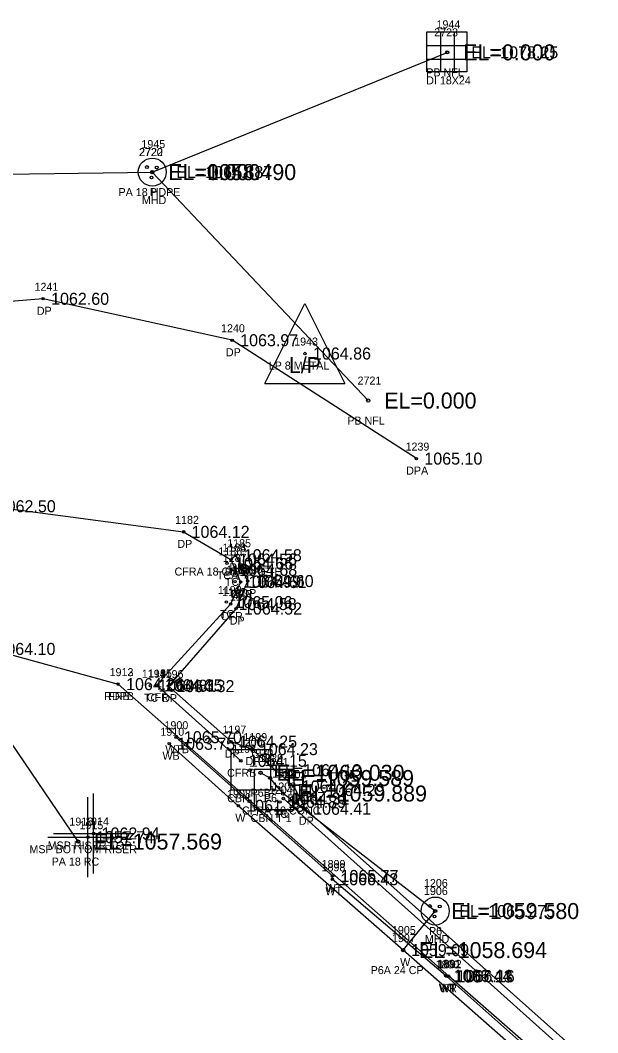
# Model space of a CAD drawing. Extents: x 1578957 to 1581675, y 1115963 to 1120391.
# Drawn here: x 1580412.6 to 1580484.8, y 1116687.4 to 1116814 of the extents above; entities that cross this region are included whole.
import ezdxf

# ---------------------------------------------------------------- set-up
doc = ezdxf.new("R2010")
doc.units = 0
for name, color, linetype in [('RD_EX_BldgApp', 7, 'Continuous'), ('RD_EX_Conc', 7, 'Continuous'), ('RD_EX_Conc_txCode', 7, 'Continuous'), ('RD_EX_DR_ErosCtrl', 7, 'Continuous'), ('RD_EX_DR_ErosCtrl_txCode', 7, 'Continuous'), ('RD_EX_DR_Inlet', 7, 'Continuous'), ('RD_EX_DR_Inlet_txCode', 7, 'Continuous'), ('RD_EX_DR_Pipe', 7, 'Continuous'), ('RD_EX_DR_Pipe_txCode', 7, 'Continuous'), ('RD_EX_Driveway', 7, 'Continuous'), ('RD_EX_Driveway_txCode', 7, 'Continuous'), ('RD_EX_Fence_Other', 7, 'Continuous'), ('RD_EX_Fence_Other_txCode', 7, 'Continuous'), ('RD_EX_Misc', 7, 'Continuous'), ('RD_EX_Misc_txCode', 7, 'Continuous'), ('RD_EX_TX_Conc_ELEV', 7, 'Continuous'), ('RD_EX_TX_DR_ErosCtrl_ELEV', 7, 'Continuous'), ('RD_EX_TX_DR_Inlet_ELEV', 7, 'Continuous'), ('RD_EX_TX_Driveway_ELEV', 7, 'Continuous'), ('RD_EX_TX_Fence_Other_ELEV', 7, 'Continuous'), ('RD_EX_TX_Misc_ELEV', 7, 'Continuous'), ('RD_EX_TX_UT_ELEV', 7, 'Continuous'), ('RD_EX_UT', 7, 'Continuous'), ('RD_EX_UT_txCode', 7, 'Continuous'), ('RD_SMD_Locator', 7, 'Continuous'), ('RD_TX_Pipe_ElevEX', 7, 'Continuous')]:
    doc.layers.add(name, color=color, linetype=linetype)

msp = doc.modelspace()

# ---------------------------------------------------------------- linework, layer by layer
at = {"layer": 'RD_EX_BldgApp'}
msp.add_lwpolyline([(1580452.9, 1116627.69), (1580465.65, 1116641.69), (1580491, 1116670.95), (1580460.48, 1116697.77), (1580439.88, 1116715.8), (1580431.25, 1116723.55)], dxfattribs=at)
at = {"layer": 'RD_EX_Conc'}
for points in [[(1580438.97, 1116746.57), (1580440.17, 1116743.76), (1580438.93, 1116741), (1580429.68, 1116730.86), (1580440.2, 1116721.42)], [(1580445.53, 1116716.71), (1580496.67, 1116670.92), (1580482, 1116654.67)]]:
    msp.add_lwpolyline(points, dxfattribs=at)
at = {"layer": 'RD_EX_DR_ErosCtrl'}
msp.add_lwpolyline([(1580451.64, 1116626.14), (1580425.19, 1116657.94), (1580401.68, 1116702.86), (1580396.66, 1116727.54), (1580408.78, 1116735.4), (1580424.86, 1116731)], dxfattribs=at)
at = {"layer": 'RD_EX_DR_Inlet'}
for p, q in [((1580465.16, 1116812.5), (1580465.16, 1116807.5)), ((1580466.86, 1116812.5), (1580466.86, 1116807.5)), ((1580463.46, 1116810.8), (1580468.46, 1116810.8)), ((1580463.46, 1116809.1), (1580468.46, 1116809.1)), ((1580443.96, 1116717.8), (1580443.96, 1116722.8)), ((1580446.88, 1116715.32), (1580446.88, 1116720.32))]:
    msp.add_line(p, q, dxfattribs=at)
for points in [[(1580463.46, 1116807.5), (1580463.46, 1116812.5), (1580468.46, 1116812.5), (1580468.46, 1116807.5)], [(1580443.96, 1116717.8), (1580443.96, 1116722.8), (1580438.96, 1116722.8), (1580438.96, 1116717.8)], [(1580446.88, 1116715.32), (1580446.88, 1116720.32), (1580441.88, 1116720.32), (1580441.88, 1116715.32)]]:
    msp.add_lwpolyline(points, close=True, dxfattribs=at)
for centre, radius in [((1580429.13, 1116794.98), 1.75), ((1580428.47, 1116795.61), 0.175), ((1580429.69, 1116795.54), 0.175), ((1580429.04, 1116794.31), 0.175), ((1580464.5, 1116702.65), 1.75), ((1580463.84, 1116703.28), 0.175), ((1580465.06, 1116703.21), 0.175), ((1580464.42, 1116701.98), 0.175)]:
    msp.add_circle(centre, radius, dxfattribs=at)
at = {"layer": 'RD_EX_DR_Pipe'}
for p, q in [((1580429.13, 1116794.98), (1580466, 1116809.94)), ((1580419.86, 1116711.33), (1580368.9, 1116786.42))]:
    msp.add_line(p, q, dxfattribs=at)
for points in [[(1580373.92, 1116794.24), (1580429.13, 1116794.98), (1580456.13, 1116766.43)], [(1580460.48, 1116697.77), (1580464.5, 1116702.65), (1580445.48, 1116717.33), (1580443.86, 1116719.27), (1580442.67, 1116719.93)]]:
    msp.add_lwpolyline(points, dxfattribs=at)
at = {"layer": 'RD_EX_Driveway'}
for points in [[(1580462.14, 1116759.18), (1580439.12, 1116773.97), (1580415.49, 1116779.15), (1580390.39, 1116777.12), (1580371.16, 1116771.09), (1580357.63, 1116768.05), (1580349.12, 1116769.69), (1580337.03, 1116778.21), (1580332.46, 1116780.72)], [(1580373.95, 1116705.15), (1580371.97, 1116717.41), (1580373.73, 1116733.05), (1580376.41, 1116737.85), (1580388.16, 1116748.03), (1580408.82, 1116753.23), (1580433.05, 1116750.03), (1580438.97, 1116746.57), (1580439.57, 1116747.11), (1580441.05, 1116743.88), (1580439.6, 1116740.44), (1580431.15, 1116730.75), (1580438.98, 1116723.82), (1580441.58, 1116722.88), (1580446.82, 1116718.23), (1580448.24, 1116715.43), (1580498.02, 1116671.05)]]:
    msp.add_lwpolyline(points, dxfattribs=at)
at = {"layer": 'RD_EX_Fence_Other'}
msp.add_lwpolyline([(1580454.05, 1116626.57), (1580466.44, 1116640.92), (1580493.01, 1116671.07), (1580466.18, 1116694.51), (1580424.86, 1116731)], dxfattribs=at)
at = {"layer": 'RD_EX_Misc'}
for p, q in [((1580421.1, 1116706.88), (1580421.1, 1116716.88)), ((1580421.8, 1116707.34), (1580421.8, 1116717.34)), ((1580416.1, 1116711.88), (1580426.1, 1116711.88)), ((1580416.8, 1116712.34), (1580426.8, 1116712.34))]:
    msp.add_line(p, q, dxfattribs=at)
msp.add_lwpolyline([(1580453.8, 1116626.93), (1580466.22, 1116641.12), (1580492.44, 1116671.09), (1580484.48, 1116677.96), (1580484.31, 1116678.14), (1580465.93, 1116694.48), (1580465.8, 1116694.58), (1580451.63, 1116706.62), (1580451.66, 1116707.03), (1580432.09, 1116724.37)], dxfattribs=at)
at = {"layer": 'RD_EX_UT'}
for p, q in [((1580443.22, 1116768.58), (1580448.22, 1116778.58)), ((1580448.22, 1116778.58), (1580453.22, 1116768.58)), ((1580443.22, 1116768.58), (1580453.22, 1116768.58))]:
    msp.add_line(p, q, dxfattribs=at)
at = {"layer": 'RD_SMD_Locator'}
for centre, radius in [((1580466, 1116809.94), 0.2), ((1580466, 1116809.94), 0.15), ((1580429.13, 1116794.98), 0.2), ((1580429.13, 1116794.98), 0.2), ((1580429.13, 1116794.98), 0.15), ((1580415.49, 1116779.15), 0.15), ((1580439.12, 1116773.97), 0.15), ((1580448.22, 1116772.31), 0.15), ((1580456.13, 1116766.43), 0.2), ((1580462.14, 1116759.18), 0.15), ((1580433.05, 1116750.03), 0.15), ((1580438.97, 1116746.57), 0.15), ((1580438.97, 1116746.57), 0.15), ((1580439.57, 1116747.11), 0.15), ((1580438.49, 1116746.08), 0.15), ((1580439, 1116745.28), 0.15), ((1580439.47, 1116743.82), 0.15), ((1580440.17, 1116743.76), 0.15), ((1580441.05, 1116743.88), 0.15), ((1580438.4, 1116741.26), 0.15), ((1580438.93, 1116741), 0.15), ((1580439.6, 1116740.44), 0.15), ((1580424.86, 1116731), 0.15), ((1580424.86, 1116731), 0.15), ((1580428.89, 1116730.8), 0.15), ((1580429.68, 1116730.86), 0.15), ((1580431.15, 1116730.75), 0.15), ((1580432.09, 1116724.37), 0.15), ((1580438.98, 1116723.82), 0.15), ((1580431.25, 1116723.55), 0.15), ((1580441.58, 1116722.88), 0.15), ((1580440.2, 1116721.42), 0.15), ((1580441.37, 1116720.25), 0.15), ((1580442.67, 1116719.93), 0.2), ((1580443.86, 1116719.27), 0.2), ((1580444.29, 1116717.77), 0.15), ((1580446.82, 1116718.23), 0.15), ((1580445.1, 1116716.29), 0.15), ((1580445.48, 1116717.33), 0.2), ((1580445.53, 1116716.71), 0.15), ((1580439.88, 1116715.8), 0.15), ((1580448.24, 1116715.43), 0.15), ((1580419.86, 1116711.33), 0.2), ((1580421.1, 1116711.88), 0.15), ((1580421.8, 1116712.34), 0.15), ((1580451.63, 1116706.62), 0.15), ((1580451.66, 1116707.03), 0.15), ((1580464.5, 1116702.65), 0.2), ((1580464.5, 1116702.65), 0.15), ((1580460.48, 1116697.77), 0.2), ((1580460.48, 1116697.77), 0.15), ((1580465.8, 1116694.58), 0.15), ((1580465.93, 1116694.48), 0.15), ((1580466.18, 1116694.51), 0.15)]:
    msp.add_circle(centre, radius, dxfattribs=at)

# ---------------------------------------------------------------- texts
at = {"layer": 'RD_EX_Conc_txCode'}
for s, p in [('1186', (1580437.4, 1116747.08)), ('1184', (1580437.91, 1116747.57)), ('1187', (1580437.94, 1116746.28)), ('CFRA 18 CONCRETE', (1580431.92, 1116744.57)), ('1188', (1580438.41, 1116744.82)), ('1189', (1580439.1, 1116744.76)), ('TCA', (1580437.2, 1116744.08)), ('TC', (1580438.21, 1116743.28)), ('1193', (1580437.33, 1116742.26)), ('1192', (1580437.86, 1116742)), ('TC', (1580438.68, 1116741.82)), ('CFR', (1580438.94, 1116741.76)), ('TC', (1580437.6, 1116739.26)), ('CFR', (1580437.7, 1116739)), ('1194', (1580427.83, 1116731.8)), ('1195', (1580428.62, 1116731.86)), ('TC', (1580428.1, 1116728.8)), ('CFR', (1580428.45, 1116728.86)), ('1198', (1580439.13, 1116722.42)), ('CFRB', (1580438.49, 1116719.42)), ('1204', (1580443.71, 1116717.29)), ('1203', (1580444.14, 1116717.71)), ('CFRA 18 CONC', (1580440.35, 1116714.71)), ('TC', (1580444.3, 1116714.29))]:
    msp.add_text(s, height=1, dxfattribs=at).set_placement(p)
at = {"layer": 'RD_EX_DR_ErosCtrl_txCode'}
for s, p in [('1912', (1580423.8, 1116732)), ('RDPB', (1580423.13, 1116729))]:
    msp.add_text(s, height=1, dxfattribs=at).set_placement(p)
at = {"layer": 'RD_EX_DR_Inlet_txCode'}
for s, p in [('1944', (1580464.66, 1116812.94)), ('DI 18X24', (1580463.37, 1116805.94)), ('1945', (1580427.78, 1116797.98)), ('MHD', (1580427.84, 1116790.98)), ('1200', (1580439.95, 1116723.25)), ('1201', (1580443.19, 1116720.77)), ('CBN T 1', (1580438.5, 1116716.25)), ('CBN T 1', (1580441.42, 1116713.77)), ('1206', (1580463.09, 1116705.65)), ('MHD', (1580463.21, 1116698.65))]:
    msp.add_text(s, height=1, dxfattribs=at).set_placement(p)
at = {"layer": 'RD_EX_DR_Pipe_txCode'}
for s, p in [('2723', (1580464.37, 1116811.94)), ('PB NFL', (1580463.38, 1116806.94)), ('2720', (1580427.46, 1116796.98)), ('2722', (1580427.5, 1116796.98)), ('PA 18 HDPE', (1580424.92, 1116791.98)), ('P', (1580428.82, 1116791.98)), ('2721', (1580454.79, 1116768.43)), ('PB NFL', (1580453.51, 1116763.43)), ('1930', (1580441.28, 1116721.93)), ('1929', (1580442.51, 1116721.27)), ('1928', (1580444.14, 1116719.33)), ('P6B', (1580441.42, 1116716.93)), ('P6', (1580443.08, 1116716.27)), ('P6', (1580444.7, 1116714.33)), ('1916', (1580418.77, 1116713.33)), ('PA 18 RC', (1580416.56, 1116708.33)), ('1906', (1580463.09, 1116704.65)), ('1905', (1580459.09, 1116699.77)), ('P6', (1580463.72, 1116699.65)), ('P6A 24 CP', (1580456.43, 1116694.77))]:
    msp.add_text(s, height=1, dxfattribs=at).set_placement(p)
at = {"layer": 'RD_EX_Driveway_txCode'}
for s, p in [('1241', (1580414.42, 1116780.15)), ('DP', (1580414.71, 1116777.15)), ('1240', (1580437.73, 1116774.97)), ('DP', (1580438.34, 1116771.97)), ('1239', (1580460.79, 1116760.18)), ('DPA', (1580460.87, 1116757.18)), ('1182', (1580431.99, 1116751.03)), ('DP', (1580432.27, 1116748.03)), ('1183', (1580437.91, 1116747.57)), ('1185', (1580438.5, 1116748.11)), ('DP', (1580438.19, 1116744.57)), ('DP', (1580438.79, 1116745.11)), ('1190', (1580439.95, 1116744.88)), ('1191', (1580438.82, 1116741.44)), ('DP', (1580440.27, 1116741.88)), ('DP', (1580438.82, 1116738.44)), ('1196', (1580430.06, 1116731.75)), ('DP', (1580430.37, 1116728.75)), ('1197', (1580437.91, 1116724.82)), ('1199', (1580440.52, 1116723.88)), ('DP', (1580438.2, 1116721.82)), ('DP', (1580440.8, 1116720.88)), ('1202', (1580445.43, 1116719.23)), ('DP', (1580446.04, 1116716.23)), ('1205', (1580446.86, 1116716.43)), ('DP', (1580447.46, 1116713.43))]:
    msp.add_text(s, height=1, dxfattribs=at).set_placement(p)
at = {"layer": 'RD_EX_Fence_Other_txCode'}
for s, p in [('1913', (1580423.8, 1116732)), ('FRB', (1580423.63, 1116729)), ('1892', (1580464.83, 1116695.51)), ('FR', (1580465.42, 1116692.51))]:
    msp.add_text(s, height=1, dxfattribs=at).set_placement(p)
at = {"layer": 'RD_EX_Misc_txCode'}
for s, p in [('1910', (1580430.15, 1116724.55)), ('1900', (1580430.66, 1116725.37)), ('WTB', (1580430.76, 1116722.37)), ('WB', (1580430.41, 1116721.55)), ('1908', (1580438.49, 1116716.8)), ('1915', (1580420.04, 1116712.88)), ('1914', (1580420.74, 1116713.34)), ('W', (1580439.51, 1116713.8)), ('MSP RISER TOP', (1580416.06, 1116710.34)), ('MSP BOTTOM RISER', (1580413.78, 1116709.88)), ('1899', (1580450.31, 1116708.03)), ('1898', (1580450.29, 1116707.62)), ('WT', (1580450.77, 1116704.62)), ('WT', (1580450.8, 1116705.03)), ('1907', (1580459.09, 1116698.77)), ('W', (1580460.11, 1116695.77)), ('1890', (1580464.54, 1116695.48)), ('1891', (1580464.73, 1116695.58)), ('WT', (1580464.94, 1116692.58)), ('WT', (1580465.07, 1116692.48))]:
    msp.add_text(s, height=1, dxfattribs=at).set_placement(p)
at = {"layer": 'RD_EX_TX_Conc_ELEV'}
for s, p in [('1064.66', (1580439.49, 1116745.33)), ('1064.56', (1580439.97, 1116745.82)), ('1064.68', (1580440, 1116744.53)), ('1064.99', (1580440.47, 1116743.07)), ('1064.61', (1580441.17, 1116743.01)), ('1065.06', (1580439.4, 1116740.51)), ('1064.58', (1580439.93, 1116740.25)), ('1064.81', (1580429.89, 1116730.05)), ('1064.35', (1580430.68, 1116730.11)), ('1064.15', (1580441.2, 1116720.67)), ('1064.89', (1580446.1, 1116715.54)), ('1064.31', (1580446.53, 1116715.96))]:
    msp.add_text(s, height=1.5, dxfattribs=at).set_placement(p)
at = {"layer": 'RD_EX_TX_DR_ErosCtrl_ELEV'}
for s, p in [('1064.10', (1580409.78, 1116734.65)), ('1064.26', (1580425.86, 1116730.25))]:
    msp.add_text(s, height=1.5, dxfattribs=at).set_placement(p)
at = {"layer": 'RD_EX_TX_DR_Inlet_ELEV'}
for s, p in [('EL=1078.25', (1580469, 1116809.19)), ('EL=1064.387', (1580432.13, 1116794.23)), ('EL=1064.13', (1580444.37, 1116719.5)), ('EL=1064.29', (1580447.29, 1116717.02)), ('EL=1065.275', (1580467.5, 1116701.9))]:
    msp.add_text(s, height=1.5, dxfattribs=at).set_placement(p)
at = {"layer": 'RD_EX_TX_Driveway_ELEV'}
for s, p in [('1062.60', (1580416.49, 1116778.4)), ('1063.97', (1580440.12, 1116773.22)), ('1065.10', (1580463.14, 1116758.43)), ('1062.50', (1580409.82, 1116752.48)), ('1064.12', (1580434.05, 1116749.28)), ('1064.56', (1580439.97, 1116745.82)), ('1064.58', (1580440.57, 1116746.36)), ('1064.60', (1580442.05, 1116743.13)), ('1064.52', (1580440.6, 1116739.69)), ('1064.32', (1580432.15, 1116730)), ('1064.25', (1580439.98, 1116723.07)), ('1064.23', (1580442.58, 1116722.13)), ('1064.27', (1580447.82, 1116717.48)), ('1064.41', (1580449.24, 1116714.68))]:
    msp.add_text(s, height=1.5, dxfattribs=at).set_placement(p)
at = {"layer": 'RD_EX_TX_Fence_Other_ELEV'}
for s, p in [('1064.26', (1580425.86, 1116730.25)), ('1066.16', (1580467.18, 1116693.76))]:
    msp.add_text(s, height=1.5, dxfattribs=at).set_placement(p)
at = {"layer": 'RD_EX_TX_Misc_ELEV'}
for s, p in [('1063.75', (1580432.25, 1116722.8)), ('1065.70', (1580433.09, 1116723.62)), ('1061.38', (1580440.88, 1116715.05)), ('1057.74', (1580422.1, 1116711.13)), ('1062.94', (1580422.8, 1116711.59)), ('1065.77', (1580452.66, 1116706.28)), ('1066.43', (1580452.63, 1116705.87)), ('1059.09', (1580461.48, 1116697.02)), ('1066.44', (1580466.8, 1116693.83)), ('1067.13', (1580466.93, 1116693.73))]:
    msp.add_text(s, height=1.5, dxfattribs=at).set_placement(p)
at = {"layer": 'RD_EX_TX_UT_ELEV'}
msp.add_text('1064.86', height=1.5, dxfattribs=at).set_placement((1580449.22, 1116771.56))
at = {"layer": 'RD_EX_UT'}
msp.add_text('L/P', height=2, dxfattribs=at).set_placement((1580446.21, 1116769.86))
at = {"layer": 'RD_EX_UT_txCode'}
for s, p in [('1943', (1580446.87, 1116773.31)), ('LP 8 METAL', (1580443.69, 1116770.31))]:
    msp.add_text(s, height=1, dxfattribs=at).set_placement(p)
at = {"layer": 'RD_TX_Pipe_ElevEX'}
for s, p in [('EL=0.000', (1580468, 1116808.94)), ('EL=1058.490', (1580431.13, 1116793.98)), ('EL=0.000', (1580431.13, 1116793.98)), ('EL=0.000', (1580458.13, 1116765.43)), ('EL=1060.030', (1580444.67, 1116718.93)), ('EL=1059.589', (1580445.86, 1116718.27)), ('EL=1059.889', (1580447.48, 1116716.33)), ('EL=1057.569', (1580421.86, 1116710.33)), ('EL=1059.580', (1580466.5, 1116701.65)), ('EL=1058.694', (1580462.48, 1116696.77))]:
    msp.add_text(s, height=2, dxfattribs=at).set_placement(p)

doc.saveas('drawing.dxf')
